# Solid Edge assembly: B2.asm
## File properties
Author: edge
Template: Jis Assembly.asm
Last saved by: edge
Revision: 4
Application: Solid Edge
Username: edge
文書内容のタイプ: 1
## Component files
C3.par
C4.par
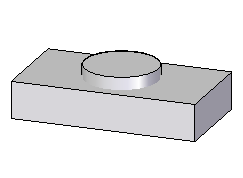
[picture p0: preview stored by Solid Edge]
